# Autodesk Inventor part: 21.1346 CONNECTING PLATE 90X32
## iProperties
Created: 2007-01
Part Number: 21.1346 CONNECTING PLATE 90X32
Document SubType Name: Modeling
Designer: Andy Moles
Material: Aluminum-6061
Mass: 108.354 g
Surface Area: 100.892 cm^2
Volume: 39.9829 cm^3
Density: 2.71 g/cm^3
Author: Andy Moles
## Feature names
1. Extrusion1
2. Hole1
3. Hole2
4. Fillet1
